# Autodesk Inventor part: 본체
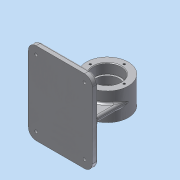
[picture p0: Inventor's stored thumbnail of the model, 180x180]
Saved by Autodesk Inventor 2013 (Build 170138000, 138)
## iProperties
Created: 2019-09
Part Number: 본체
Material: 알루미늄 6061
Document SubType Name: Modeling
Designer: Administrator
Density: 2.71 g/cm^3
Mass: 556.349 g
Surface Area: 496.821 cm^2
Volume: 205.295 cm^3
Author: Administrator
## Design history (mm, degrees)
sketch "스케치2"
  geometry: C1 r 32 at (0, 0); 1 further point
  constraints: 1 centre point, 1 coincident
  dimensions: "d0" = 64 diameter of C1
extrude "돌출1" new body sketch "스케치2" stored distance "d2" = 42; taper "d3" = 0 deg
sketch "스케치3"
  geometry: C1 r 32 at (0, 0) reference; C2 r 21 at (0, 0)
  constraints: 1 centre point, 1 coincident
  dimensions: "d4" = 42 diameter of C2
extrude "돌출2" cut sketch "스케치3" distance "d5" = 15; taper "d6" = 0 deg
sketch "스케치4"
  geometry: C1 r 21 at (0, 0) reference; C2 r 18 at (0, 0)
  constraints: 1 centre point, 1 coincident
  dimensions: "d7" = 36 diameter of C2
extrude "돌출3" cut sketch "스케치4" distance "d8" = 6; taper "d9" = 0 deg
node "작업 평면1"
sketch "스케치9"
  geometry: L1 (62, 63)-(-36, 63); L2 (-36, 63)-(-36, -63); L3 (-36, -63)-(62, -63); L4 (62, -63)-(62, 63); 1 further point
  constraints: 8 end point, 2 parallel, 1 horizontal, 1 perpendicular
  dimensions: "d28" = 98 distance of L2.end L3.end; "d30" = 126 distance of L1.end L2.end; "d31" = 63 distance from line of point (0, 0) L3; "d32" = 62 distance from line of point (0, 0) L4
extrude "돌출8" join sketch "스케치9" distance "d33" = 9; taper "d34" = 0 deg
sketch "스케치10"
  geometry: L1 (32, -4)-(-32, -4); L2 (-32, -4)-(-32, 4); L3 (-32, 4)-(32, 4); L4 (32, 4)-(32, -4); L5 (32, -4)-(-32, 4); L6 (-32, -4)-(32, 4); L7 (-4, -17)-(4, -17); L8 (4, -17)-(4, 17); L9 (4, 17)-(-4, 17); L10 (-4, 17)-(-4, -17); L11 (-4, -17)-(4, 17); L12 (4, -17)-(-4, 17); 1 further point
  constraints: 24 end point, 4 midpoint, 4 parallel, 2 horizontal, 2 perpendicular
  dimensions: "d35" = 64 distance of L2.end L3.end; "d36" = 8 distance of L1.end L2.end; "d37" = 8 distance of L9.end L8.end; "d38" = 34 distance of L8.end L7.end
extrude "돌출9" join sketch "스케치10" stored distance "d39" = 9; taper "d40" = 0 deg
fillet "모깎기1" dims "d41" = 12
sketch "스케치11" dims "d44" = 52
  geometry: L1 (-24, -59)-(50, -59) reference; C1 r 32 at (0, 0) reference; 2 further points
  constraints: 1 coincident, 1 horizontal alignment, 2 other
  dimensions: "d43" = 59 distance from line of L1 point (-26, 0)
hole "구멍1" sketch "스케치11" at (-26, 0) diameter "d45" = 3.242; stored, may be unused: countersink angle "d49" = 90 deg, drill point angle "d51" = 118 deg; dims "d46" = 8, "d47" = 4, "d48" = 2, "d50" = 10
sketch "스케치12"
  geometry: A1 r 12 centre (-50, 51) between (-50, 63) and (-62, 51) reference; A2 r 12 centre (24, 51) between (36, 51) and (24, 63) reference; 3 further points
  constraints: 2 coincident
hole "구멍2" sketch "스케치12" at (-50, 51), (24, 51) diameter "d58" = 4.5; stored, may be unused: countersink angle "d62" = 90 deg, drill point angle "d64" = 118 deg; dims "d59" = 8, "d60" = 8, "d61" = 4.4, "d63" = 10
fillet "모깎기2" dims "d68" = 0.3
chamfer "모따기1" distance "d69" = 1; stored, may be unused: second distance "d70" = 2, angle "d71" = 45 deg
fillet "모깎기3" dims "d72" = 3
fillet "모깎기4" dims "d73" = 3
fillet "모깎기5" dims "d74" = 3
fillet "모깎기6" dims "d75" = 3
sketch "스케치13"
  geometry: L1 (-59, -51)-(-59, 51) reference; L2 (24, 63)-(-50, 63) reference; 2 further points
  constraints: 1 other
  dimensions: "d76" = 63 distance from line of L2 point (-49, 0); "d77" = 10 distance from line of L1 point (-49, 0)
feature "엠보싱1" sketch "스케치13" dims "d28" = 98, "d30" = 126, "d31" = 63, "d32" = 62, "d78" = 0.5, "d79" = 0
node "솔리드1"
mirror "대칭1"
pattern_circular "원형 패턴1" dims angle "d53" = 360 deg
mirror "대칭2"
pattern_linear "직사각형 패턴1" dims "d67" = 102
other parameters: "d12" = -59
